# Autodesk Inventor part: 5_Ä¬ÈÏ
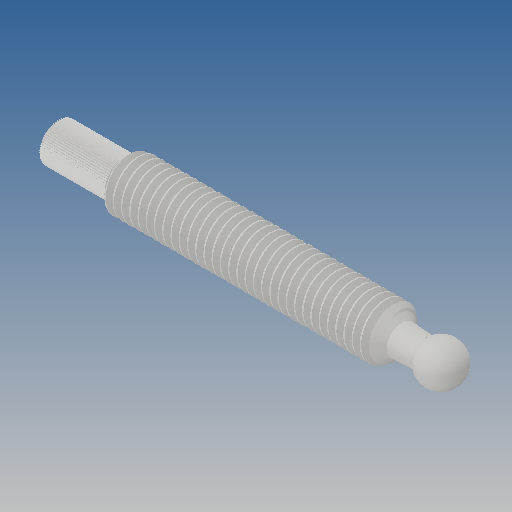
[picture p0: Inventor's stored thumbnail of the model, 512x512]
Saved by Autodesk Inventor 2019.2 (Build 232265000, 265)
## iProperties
Created: 2010-06
Part Number: 5_Ä¬ÈÏ
Material: Ogólny
Document SubType Name: Modeling
Designer: CADENGINEERING4
Density: 1 g/cm^3
Appearance: Domyślna
Author: CADENGINEERING4
Revision Number: ÈÎºÎ
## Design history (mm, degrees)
feature "NONE"
node "Bryła1"
